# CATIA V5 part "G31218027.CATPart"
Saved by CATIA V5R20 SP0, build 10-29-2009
Part number: G31218027
Revision: 9
Definition: design
Nomenclature: G31218027
Source: made
Description: NOT SPECIFIED
Bounding box of the stored display mesh (mm): x -8 to 27, y -15.5 to 15.5, z -15.5 to 15.5
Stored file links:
  C:\Users\Raffaele\Desktop\3D X SITO CF\BOLEX\23-BUSH REF 312\G31218027.CATPart

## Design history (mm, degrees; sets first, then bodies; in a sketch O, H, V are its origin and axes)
Body1 "MANIFOLD_SOLID_BREP #8059" (main body)
  Solid1: solid without history
Body2 "MANIFOLD_SOLID_BREP #8202"
  Solid2: solid without history
Body3 "MANIFOLD_SOLID_BREP #8345"
  Solid3: solid without history
Body4 "MANIFOLD_SOLID_BREP #8488"
  Solid4: solid without history
Body5 "MANIFOLD_SOLID_BREP #8631"
  Solid5: solid without history
Body6 "MANIFOLD_SOLID_BREP #8776"
  Solid6: solid without history
Body7 "MANIFOLD_SOLID_BREP #8921"
  Solid7: solid without history
Body8 "MANIFOLD_SOLID_BREP #9066"
  Solid8: solid without history
Body9 "MANIFOLD_SOLID_BREP #9211"
  Solid9: solid without history
Body10 "MANIFOLD_SOLID_BREP #9356"
  Solid10: solid without history
Body11 "MANIFOLD_SOLID_BREP #9501"
  Solid11: solid without history
Body12 "MANIFOLD_SOLID_BREP #9646"
  Solid12: solid without history
Body13 "MANIFOLD_SOLID_BREP #9791"
  Solid13: solid without history
Body14 "MANIFOLD_SOLID_BREP #9936"
  Solid14: solid without history
Body15 "MANIFOLD_SOLID_BREP #10081"
  Solid15: solid without history
Body16 "MANIFOLD_SOLID_BREP #10226"
  Solid16: solid without history
Body17 "MANIFOLD_SOLID_BREP #10371"
  Solid17: solid without history
Body18 "MANIFOLD_SOLID_BREP #10517"
  Solid18: solid without history
Body19 "MANIFOLD_SOLID_BREP #10663"
  Solid19: solid without history
Body20 "MANIFOLD_SOLID_BREP #10810"
  Solid20: solid without history
Body21 "MANIFOLD_SOLID_BREP #10957"
  Solid21: solid without history
Body22 "MANIFOLD_SOLID_BREP #11102"
  Solid22: solid without history
Body23 "MANIFOLD_SOLID_BREP #11249"
  Solid23: solid without history
Body24 "MANIFOLD_SOLID_BREP #11396"
  Solid24: solid without history
Body25 "MANIFOLD_SOLID_BREP #11541"
  Solid25: solid without history
Body26 "MANIFOLD_SOLID_BREP #11686"
  Solid26: solid without history
Body27 "MANIFOLD_SOLID_BREP #11831"
  Solid27: solid without history
Body28 "MANIFOLD_SOLID_BREP #11976"
  Solid28: solid without history
Body29 "MANIFOLD_SOLID_BREP #12121"
  Solid29: solid without history
Body30 "MANIFOLD_SOLID_BREP #12266"
  Solid30: solid without history
Body31 "MANIFOLD_SOLID_BREP #12411"
  Solid31: solid without history
Body32 "MANIFOLD_SOLID_BREP #12554"
  Solid32: solid without history
Body33 "MANIFOLD_SOLID_BREP #12697"
  Solid33: solid without history
Body34 "MANIFOLD_SOLID_BREP #12843"
  Solid34: solid without history
Body35 "MANIFOLD_SOLID_BREP #12989"
  Solid35: solid without history
Body36 "MANIFOLD_SOLID_BREP #13136"
  Solid36: solid without history
Body37 "MANIFOLD_SOLID_BREP #13283"
  Solid37: solid without history
Body38 "MANIFOLD_SOLID_BREP #13428"
  Solid38: solid without history
Body39 "MANIFOLD_SOLID_BREP #13575"
  Solid39: solid without history
Body40 "MANIFOLD_SOLID_BREP #13722"
  Solid40: solid without history
Body41 "MANIFOLD_SOLID_BREP #13867"
  Solid41: solid without history
Body42 "MANIFOLD_SOLID_BREP #14012"
  Solid42: solid without history
Body43 "MANIFOLD_SOLID_BREP #14157"
  Solid43: solid without history
Body44 "MANIFOLD_SOLID_BREP #14302"
  Solid44: solid without history
Body45 "MANIFOLD_SOLID_BREP #14447"
  Solid45: solid without history
Body46 "MANIFOLD_SOLID_BREP #14592"
  Solid46: solid without history
Body47 "MANIFOLD_SOLID_BREP #14737"
  Solid47: solid without history
Body48 "MANIFOLD_SOLID_BREP #14883"
  Solid48: solid without history
Body49 "MANIFOLD_SOLID_BREP #15029"
  Solid49: solid without history
Body50 "MANIFOLD_SOLID_BREP #15176"
  Solid50: solid without history
Body51 "MANIFOLD_SOLID_BREP #15323"
  Solid51: solid without history
Body52 "MANIFOLD_SOLID_BREP #15468"
  Solid52: solid without history
Body53 "MANIFOLD_SOLID_BREP #15615"
  Solid53: solid without history
Body54 "MANIFOLD_SOLID_BREP #15762"
  Solid54: solid without history
Body55 "MANIFOLD_SOLID_BREP #15907"
  Solid55: solid without history
Body56 "MANIFOLD_SOLID_BREP #16050"
  Solid56: solid without history
Body57 "MANIFOLD_SOLID_BREP #16193"
  Solid57: solid without history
